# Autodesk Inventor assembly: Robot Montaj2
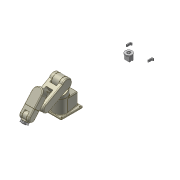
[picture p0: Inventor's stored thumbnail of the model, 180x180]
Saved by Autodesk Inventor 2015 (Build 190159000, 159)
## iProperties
Created: 2014-10
Part Number: Robot Montaj2
Document SubType Name: Assembly
Designer: nkaya
Author: nkaya
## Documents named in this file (9)
- G:\yedek\nkaya\word_doc\guz_lisans_2005\04_mtgp\2014_2015_Inventor\Hafta 04\Assembly Örnek Robot\files\Robot Montaj2.iam
- G:\yedek\nkaya\word_doc\guz_lisans_2005\04_mtgp\2014_2015_Inventor\Hafta 04\Assembly Örnek Robot\files\Robot-Base-Model-A.ipt
- G:\yedek\nkaya\word_doc\guz_lisans_2005\04_mtgp\2014_2015_Inventor\Hafta 04\Assembly Örnek Robot\files\Robot-Axis1-2.ipt
- G:\yedek\nkaya\word_doc\guz_lisans_2005\04_mtgp\2014_2015_Inventor\Hafta 04\Assembly Örnek Robot\files\Robot-Axis2-3.ipt
- G:\yedek\nkaya\word_doc\guz_lisans_2005\04_mtgp\2014_2015_Inventor\Hafta 04\Assembly Örnek Robot\files\Robot-Axis3-4.ipt
- G:\yedek\nkaya\word_doc\guz_lisans_2005\04_mtgp\2014_2015_Inventor\Hafta 04\Assembly Örnek Robot\files\Robot-Axis4-5.ipt
- G:\yedek\nkaya\word_doc\guz_lisans_2005\04_mtgp\2014_2015_Inventor\Hafta 04\Assembly Örnek Robot\files\Robot-Axis5.ipt
- G:\yedek\nkaya\word_doc\guz_lisans_2005\04_mtgp\2014_2015_Inventor\Hafta 04\Assembly Örnek Robot\files\Robot-Axis5-Adapter.ipt
- C:\Users\Public\Documents\Autodesk\Inventor 2015\inventor_2015_get_started\tutorial files\Robot-GripperAssy.iam
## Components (8 placed, 8 different names)
1. Robot-Base-Model-A:1 — Mate:1, Mate:2, Angle:1
2. Robot-Axis1-2:1 — Mate:1, Mate:2, Angle:1, Mate:3, Mate:4
3. Robot-Axis2-3:1 — Mate:3, Mate:4, Mate:5, Mate:6, Angle:2
4. Robot-Axis3-4:1 — Mate:5, Mate:6, Angle:2, Insert:1, Angle:3
5. Robot-Axis4-5:1 — Insert:1, Angle:3, Mate:7, Mate:8
6. Robot-Axis5:1 — Insert:2, Mate:7, Mate:8
7. Robot-Axis5-Adapter:1 — Insert:2
8. Robot-GripperAssy:1 [sub-assembly]
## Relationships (13: Mate 8, Angle 3, Insert 2)
- Mate:1: Robot-Base-Model-A:1 ↔ Robot-Axis1-2:1
- Mate:2: Robot-Base-Model-A:1 ↔ Robot-Axis1-2:1
- Angle:1: Robot-Base-Model-A:1 ↔ Robot-Axis1-2:1
- Mate:3: Robot-Axis1-2:1 ↔ Robot-Axis2-3:1
- Mate:4: Robot-Axis1-2:1 ↔ Robot-Axis2-3:1
- Mate:5: Robot-Axis2-3:1 ↔ Robot-Axis3-4:1
- Mate:6: Robot-Axis2-3:1 ↔ Robot-Axis3-4:1
- Angle:2: Robot-Axis2-3:1 ↔ Robot-Axis3-4:1
- Insert:1: Robot-Axis3-4:1 ↔ Robot-Axis4-5:1
- Angle:3: Robot-Axis3-4:1 ↔ Robot-Axis4-5:1
- Insert:2: Robot-Axis5:1 ↔ Robot-Axis5-Adapter:1
- Mate:7: Robot-Axis4-5:1 ↔ Robot-Axis5:1
- Mate:8: Robot-Axis4-5:1 ↔ Robot-Axis5:1
